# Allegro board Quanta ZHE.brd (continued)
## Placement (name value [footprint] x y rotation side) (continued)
PC221  *0.1u/16V_4  [C0402]  140.49 24.94 0 bottom
PC222  0.1u/50V_6  [C0603]  151.42 24.56 90 bottom
PC223  *0.1u/16V_4  [C0402]  140.49 23.93 0 bottom
PC224  22u/6.3V_6  [C0603]  148.75 22.5 90 bottom
PC225  0.1u/16V_4  [C0402]  141.89 20.88 270 bottom
PC226  0.033u/16V_4  [C0402]  143.92 20.88 90 bottom
PC227  10u/6.3V_6  [C0603]  146.84 20.75 90 bottom
PC228  22u/6.3V_8  [C0805]  149 19.35 270 bottom
PC229  22u/6.3V_8  [C0805]  151.04 19.35 270 bottom
PC230  22u/6.3V_6  [C0603]  164.62 17.83 180 bottom
PC231  22u/6.3V_6  [C0603]  164.62 16.31 180 bottom
PC232  10u/25V_8  [C0805]  137.7 14.91 270 bottom
PC233  2200p/50V_4  [C0402]  139.22 14.91 270 bottom
PC234  *47p/50V_4  [C0402]  100.36 15.29 90 bottom
PC235  *47p/50V_4  [C0402]  102.52 14.78 90 bottom
PC236  22u/6.3V_6  [C0603]  164.62 14.78 180 bottom
PC237  22u/25V_8  [C0805]  88.83 13.38 0 bottom
PD1  P4SMAFJ20A  [D-3_8X2_5]  29.95 100.84 270 top
PD2  PDZ5.6B  [DSM]  103.03 13.51 270 top
PD3  PDZ5.6B  [DSM]  104.98 13.51 270 top
PD4  SV1040  [D-TO277_213-6_1X4_3]  18.12 77.9 90 bottom
PJ1  *S_3720  [SHORT3720]  46.13 79.81 270 top
PJ2  *S_3720  [SHORT3720]  29.5 73.33 270 top
PJ3  *S_3720  [SHORT3720]  148.11 72.06 180 top
PJ4  *S_3720  [SHORT3720]  117.89 15.92 0 top
PJ5  CI2504P1H02-RB-NH  [50320-0040N-001-4P-L-SMT]  30.04 100.11 90 bottom
PJ6  *S_3720  [SHORT3720]  125.89 77.34 90 bottom
PJ7  *S_3720  [SHORT3720]  124.7 66.39 180 bottom
PJ8  *S_3720  [SHORT3720]  136.68 65.45 90 bottom
PJ9  *S_3720  [SHORT3720]  24.8 64.95 270 bottom
PJ10  *S_3720  [SHORT3720]  155.86 60.25 0 bottom
PJ11  *S_3720  [SHORT3720]  161.96 39.67 90 bottom
PJ12  *S_3720  [SHORT3720]  155.99 37.9 180 bottom
PJ13  *S_3720  [SHORT3720]  155.99 32.31 180 bottom
PJ14  *S_3720  [SHORT3720]  144.18 17.58 270 bottom
PJ15  *S_3720  [SHORT3720]  161.07 17.45 270 bottom
PJ16  50458-00801-V02  [50458-00801-V02-8P-L]  98.35 7.52 180 bottom
PL1  2.2uH_2.5x2.0x1.2  [L2_5X2-1_2H]  114.08 13.26 0 top
PL2  0.15uH/36A_7x7x4  [L6_6X6_6-3_8]  58.96 80.31 0 bottom
PL3  0.68uH_7x7x3  [CHOKE-PCMC063T-3R3MN-SMT]  136.56 78.92 180 bottom
PL4  0.47uH/17.5A_7X7X3  [CHOKE-PCMC063T-3R3MN-SMT]  41.94 74.98 0 bottom
PL5  1uH_7x7x3  [CHOKE-PCMC063T-3R3MN-SMT]  127.84 71.68 180 bottom
PL6  2.2uH_2.5x2.0x1.2  [L2_5X2-1_2H]  21.24 64.18 0 bottom
PL7  1uH/11A_7x7x3  [CHOKE-PCMC063T-3R3MN-SMT]  155.73 53.9 90 bottom
PL8  1uH/11A_7x7x3  [CHOKE-PCMC063T-3R3MN-SMT]  162.59 24.18 270 bottom
PL9  1uH/11A_7x7x3  [CHOKE-PCMC063T-3R3MN-SMT]  155.61 21.39 270 bottom
PL10  6.8uH_7x7x3  [CHOKE-PCMC063T-3R3MN-SMT]  128.18 15.42 180 bottom
PQ1  2N7002K  [SOT23_213-3_3-2]  109.96 84 270 top
PQ2  AO3404  [SOT23_213-3_3-2]  143.03 70.15 90 top
PQ3  VL@2N7002K  [SOT23_213-3_3-2]  169.93 65.3 270 top
PQ4  VL@DDTC144EUA-7-F  [UMT_213-3-1_3]  166.61 64.95 90 top
PQ5  VL@2N7002K  [SOT23_213-3_3-2]  158.78 62.15 270 top
PQ6  VL@AO3415  [SOT23_213-3_3-2]  162.49 62.15 270 top
PQ7  2N7002K  [SOT23_213-3_3-2]  157.13 57.96 270 top
PQ8  2N7002K  [SOT23_213-3_3-2]  158.88 53.47 180 top
PQ9  *2N7002K  [SOT23_213-3_3-2]  115.98 37.26 90 top
PQ10  *AO3404  [SOT23_213-3_3-2]  116.11 33.07 90 top
PQ11  2N7002K  [SOT23_213-3_3-2]  158.66 32.69 270 top
PQ12  DDTC144EUA-7-F  [UMT_213-3-1_3]  155.28 32.31 270 top
PQ13  AON6414AL  [POWER-5_2X5_55-1_27-5P]  127.54 15.29 180 top
PQ14  AON6414AL  [POWER-5_2X5_55-1_27-5P]  50.96 75.87 0 bottom
PQ15  AON7752  [DFN-8L-3X3-65-5P-0_9H]  35.21 74.85 180 bottom
PQ16  AON6792  [POWER-5_2X5_55-1_27-5P]  57.82 73.71 0 bottom
PQ17  AON6414AL  [POWER-5_2X5_55-1_27-5P]  19.18 71.5 0 bottom
PQ18  AON7410  [DFN-8L-3X3-65-5P-0_9H]  36.35 71.17 0 bottom
PQ19  AO3404  [SOT23_213-3_3-2]  24.42 60.88 270 bottom
PQ20  AON7752  [DFN-8L-3X3-65-5P-0_9H]  153.37 28.17 180 bottom
PQ21  AON7410  [DFN-8L-3X3-65-5P-0_9H]  157.26 27.99 270 bottom
PQ22  AON7410  [DFN-8L-3X3-65-5P-0_9H]  134.65 17.74 0 bottom
PQ23  AON7410  [DFN-8L-3X3-65-5P-0_9H]  134.65 13.93 180 bottom
PQ24  *2N7002K  [SOT23_213-3_3-2]  138.21 7.42 90 bottom
PR1  22_5%_8  [R0805]  110.73 86.92 0 top
PR2  100_1%_4  [R0402]  65.56 85.14 0 top
PR3  100_1%_4  [R0402]  65.56 84.12 180 top
PR4  10_5%_6  [R0603]  143.16 83.23 180 top
PR5  2.2_5%_6  [R0603]  143.16 81.81 180 top
PR6  *S_4  [S0402]  148.5 78.79 90 top
PR7  *S_4  [S0402]  149.51 78.79 90 top
PR8  *0_5%_4  [R0402]  148.5 77.01 90 top
PR9  100K_1%_4  [R0402]  149.51 77.01 270 top
PR10  *S_4  [S0402]  41.94 76.12 90 top
PR11  *S_4  [S0402]  42.96 76.12 270 top
PR12  *2.2_5%_6  [R0603]  56.42 73.71 180 top
PR13  2.2_5%_6  [R0603]  56.42 72.19 180 top
PR14  3.3_5%_6  [R0603]  59.21 72.19 0 top
PR15  4.02K_1%_4  [R0402]  16.67 71.42 0 top
PR16  47.5K_1%_4  [R0402]  27.72 70.41 0 top
PR17  VL@1M_5%_6  [R0603]  175.93 70.41 0 top
PR18  *160_1%_4  [R0402]  49.94 70.03 0 top
PR19  *S_6  [S0603]  39.66 69.77 270 top
PR20  VL@1M_5%_6  [R0603]  173.51 69.65 270 top
PR21  324_1%_4  [R0402]  27.72 69.39 0 top
PR22  VL@22_5%_8  [R0805]  171.74 69.26 90 top
PR23  *200_1%_4  [R0402]  48.29 68.76 90 top
PR24  6.04K_1%_4  [R0402]  27.72 68.25 0 top
PR25  *S_4  [S0402]  38.13 67.56 180 top
PR26  *240_1%_4  [R0402]  49.82 67.49 0 top
PR27  3.83K_1%_4  [R0402]  27.72 67.11 0 top
PR28  121K_1%_4  [R0402]  29.62 67.11 0 top
PR29  95.3_1%_4  [R0402]  38.13 66.34 180 top
PR30  3.9_1%_4  [R0402]  27.72 65.96 0 top
PR31  20.5K_1%_4  [R0402]  29.62 65.96 0 top
PR32  *0_5%_4  [R0402]  49.82 65.45 0 top
PR33  20_1%_4  [R0402]  38.13 65.2 180 top
PR34  VL@0_5%_4  [R0402]  159.16 65.07 0 top
PR35  *VL@100K_1%_6  [R0603]  163.74 65.07 180 top
PR36  30.1K_1%_4  [R0402]  29.62 64.82 180 top
PR37  VL@0_5%_4  [R0402]  161.32 64.82 180 top
PR38  22_5%_6  [R0603]  46.26 64.44 180 top
PR39  100_1%_4  [R0402]  43.21 64.06 270 top
PR40  100_1%_4  [R0402]  44.23 64.06 270 top
PR41  402_1%_4  [R0402]  27.72 63.68 180 top
PR42  *S_4  [S0402]  29.62 63.68 0 top
PR43  *S_4  [S0402]  39.91 63.55 90 top
PR44  *1K_1%_4  [R0402]  41.05 63.55 90 top
PR45  20K_1%_4  [R0402]  49.82 63.42 0 top
PR46  280_1%_4  [R0402]  48.04 62.91 0 top
PR47  402_1%_4  [R0402]  27.72 62.53 180 top
PR48  680_1%_4  [R0402]  49.82 62.41 0 top
PR49  *S_4  [S0402]  56.55 62.15 0 top
PR50  16.9K_1%_4  [R0402]  51.34 61.77 90 top
PR51  1K_1%_4  [R0402]  27.72 61.39 180 top
PR52  110_1%_4  [R0402]  49.82 61.39 0 top
PR53  57.6K_1%_4  [R0402]  32.67 61.26 270 top
PR54  *S_4  [S0402]  33.81 61.26 270 top
PR55  2.15K_1%_4  [R0402]  34.96 61.26 270 top
PR56  22.6K_1%_4  [R0402]  36.1 61.26 270 top
PR57  68K_1%_4  [R0402]  37.24 61.26 270 top
PR58  *S_4  [S0402]  56.55 61.01 0 top
PR59  22_5%_8  [R0805]  155.23 60.88 180 top
PR60  *S_4  [S0402]  30.64 60.5 90 top
PR61  *S_4  [S0402]  31.66 60.5 90 top
PR62  182_1%_4  [R0402]  51.59 59.87 90 top
PR63  *S_4  [S0402]  52.86 61.39 270 top
PR64  VL@100K_1%_4  [R0402]  161.58 59.74 0 top
PR65  221K_1%_4  [R0402]  37.62 59.61 0 top
PR66  215K_1%_4  [R0402]  34.96 59.23 270 top
PR67  100K_1%_4  [R0402]  36.1 59.23 270 top
PR68  VL@10K_5%_4  [R0402]  159.54 58.72 270 top
PR69  VL@0_5%_8  [R0805]  161.45 55.29 0 top
PR70  22_5%_8  [R0805]  161.8 52.58 270 top
PR71  *S_6  [S0603]  153.7 50.6 90 top
PR72  10_1%_6  [R0603]  155.23 50.6 90 top
PR73  *4.7_5%_6  [R0603]  158.91 49.07 0 top
PR74  *10K_1%_4  [R0402]  157.13 46.66 0 top
PR75  *1K_1%_4  [R0402]  155.61 46.28 90 top
PR76  1K_1%_4  [R0402]  156.37 44.5 0 top
PR77  1M_5%_6  [R0603]  158.66 35.86 90 top
PR78  1M_5%_6  [R0603]  153.7 35.61 90 top
PR79  *22_5%_8  [R0805]  113.06 34.97 270 top
PR80  *S_6  [S0603]  166.78 33.32 90 top
PR81  *4.7_5%_6  [R0603]  163.74 30.4 270 top
PR82  1M_5%_6  [R0603]  159.04 30.02 180 top
PR83  *100K_1%_6  [R0603]  155.35 29.77 180 top
PR84  10_1%_6  [R0603]  166.78 27.74 270 top
PR85  *4.7_5%_6  [R0603]  153.83 27.48 270 top
PR86  *4.7_5%_6  [R0603]  132.62 17.96 180 top
PR87  316K_1%_4  [R0402]  139.1 15.29 270 top
PR88  100K_1%_4  [R0402]  141.13 15.29 270 top
PR89  10K_5%_4  [R0402]  146.97 15.54 270 top
PR90  *0_5%_4  [R0402]  147.99 15.29 270 top
PR91  *S_4  [S0402]  149 15.29 270 top
PR92  *S_6  [S0603]  142.63 15.16 90 top
PR93  *S_6  [S0603]  144.23 15.16 90 top
PR94  10_1%_6  [R0603]  145.7 15.16 90 top
PR95  *S_6  [S0603]  110.4 14.65 90 top
PR96  *S_6  [S0603]  121.83 14.4 90 top
PR97  *10K_5%_4  [R0402]  148.11 13.89 180 top
PR98  *S_4  [S0402]  154.59 13.38 90 top
PR99  *S_4  [S0402]  155.61 13.38 270 top
PR100  *S_4  [S0402]  156.62 13.38 270 top
PR101  100K_5%_4  [R0402]  148.11 12.88 180 top
PR104  *S_6  [S0603]  139.35 11.86 180 top
PR105  *S_4  [S0402]  148.11 11.86 180 top
PR106  *S_4  [S0402]  148.11 10.84 180 top
PR107  *S_4  [S0402]  148.11 9.83 180 top
PR108  *100K_5%_4  [R0402]  150.15 9.83 0 top
PR109  *S_4  [S0402]  109 9.32 270 top
PR110  *0_5%_4  [R0402]  148.11 8.81 180 top
PR112  *S_4  [S0402]  148.11 7.8 180 top
PR113  *SP@15.4K_1%_4  [R0402]  150.15 7.8 180 top
PR114  100K_1%_4  [R0402]  109 7.54 270 top
PR115  15K_1%_4  [R0402]  110.27 7.54 90 top
PR116  47.5K_1%_4  [R0402]  111.28 7.54 270 top
PR117  *S_4  [S0402]  112.3 7.54 270 top
PR118  *S_4  [S0402]  113.32 7.54 90 top
PR119  10K_5%_4  [R0402]  114.33 7.54 90 top
PR120  *0_5%_4  [R0402]  115.35 7.54 270 top
PR121  4.02K_1%_4  [R0402]  143.67 6.91 270 top
PR122  *S_4  [S0402]  144.69 6.91 90 top
PR123  137K_1%_4  [R0402]  145.7 6.91 270 top
PR124  *S_4  [S0402]  146.72 6.91 90 top
PR125  20_5%_12  [R1206]  138.97 5.64 90 top
PR126  100K_1%_4  [R0402]  143.67 4.88 90 top
PR127  100K_1%_4  [R0402]  144.69 4.88 270 top
PR128  866K_1%_4  [R0402]  145.7 4.88 270 top
PR130  *S_4  [S0402]  110.01 86.79 0 bottom
PR131  150_1%_4  [R0402]  113.71 86.92 90 bottom
PR132  *4.7_5%_6  [R0603]  139.61 83.11 0 bottom
PR133  30.1K_1%_4  [R0402]  109.38 82.47 180 bottom
PR134  1K_NTC_4_3%  [R0402]  43.34 78.92 0 bottom
PR135  *S_4  [S0402]  64.93 78.03 180 bottom
PR136  1K_NTC_4_3%  [R0402]  66.83 78.03 0 bottom
PR137  *2.2_5%_6  [R0603]  36.1 77.52 0 bottom
PR138  *S_4  [S0402]  148.24 77.27 90 bottom
PR139  *S_4  [S0402]  150.27 77.27 90 bottom
PR140  *S_4  [S0402]  64.93 77.01 180 bottom
PR141  6.34K_1%_4  [R0402]  148.24 75.49 270 bottom
PR142  20K_1%_4  [R0402]  150.27 75.49 270 bottom
PR143  100K_1%_4  [R0402]  135.03 74.98 0 bottom
PR144  *S_4  [S0402]  137.95 74.98 180 bottom
PR145  10K_1%_4  [R0402]  139.86 74.98 180 bottom
PR146  73.2K_1%_4  [R0402]  146.34 74.34 0 bottom
PR147  *S_4  [S0402]  133.64 73.96 270 bottom
PR148  *S_4  [S0402]  136.81 73.96 0 bottom
PR149  10K_1%_4  [R0402]  139.22 72.95 180 bottom
PR150  0.01_1%_0612  [RC3216]  24.57 72.21 270 bottom
PR151  10K_1%_4  [R0402]  49.82 71.55 0 bottom
PR152  *S_6  [S0603]  52.23 71.04 90 bottom
PR154  1K_1%_4  [R0402]  61.88 70.41 180 bottom
PR155  57.6K_1%_4  [R0402]  63.91 69.01 90 bottom
PR156  *S_4  [S0402]  49.82 70.03 0 bottom
PR157  121K_1%_4  [R0402]  58.58 69.77 270 bottom
PR158  2.2_5%_6  [R0603]  30.64 69.77 180 bottom
PR159  100K_NTC_4_1%  [R0402]  39.91 69.77 270 bottom
PR160  100K_NTC_4_1%  [R0402]  57.56 69.77 270 bottom
PR161  9.53K_1%_4  [R0402]  59.6 69.77 90 bottom
PR162  0_5%_4  [R0402]  61.88 69.39 180 bottom
PR163  *S_4  [S0402]  23.88 69.34 270 bottom
PR164  *S_4  [S0402]  24.97 69.34 270 bottom
PR166  95.3_1%_4  [R0402]  49.82 69.01 0 bottom
PR167  10_5%_6  [R0603]  139.08 68.79 270 bottom
PR168  3.3_5%_6  [R0603]  30.64 68.25 180 bottom
PR169  3.9_1%_4  [R0402]  59.98 68.25 180 bottom
PR170  *2.2_5%_6  [R0603]  132.87 68.25 90 bottom
PR171  *S_4  [S0402]  49.82 67.87 0 bottom
PR172  40.2K_1%_4  [R0402]  58.45 67.87 90 bottom
PR173  110K_5%_4  [R0402]  17 67.84 180 bottom
PR174  *S_4  [S0402]  157.39 67.61 180 bottom
PR175  10K_1%_4  [R0402]  38.13 67.49 180 bottom
PR176  21.5K_1%_4  [R0402]  59.98 67.23 180 bottom
PR177  *S_4  [S0402]  61.88 67.23 180 bottom
PR178  *S_8  [S0805]  160.43 66.85 180 bottom
PR179  20_1%_4  [R0402]  49.82 66.72 0 bottom
PR180  *S_4  [S0402]  157.39 66.6 0 bottom
PR181  160_1%_4  [R0402]  40.16 66.34 0 bottom
PR182  365_1%_4  [R0402]  61.5 66.09 0 bottom
PR183  604_1%_4  [R0402]  58.33 65.71 90 bottom
PR184  *S_4  [S0402]  157.39 65.58 180 bottom
PR185  *10K_1%_4  [R0402]  49.82 65.45 180 bottom
PR186  *S_4  [S0402]  38.13 65.2 180 bottom
PR187  *200_1%_4  [R0402]  40.16 65.2 0 bottom
PR188  *S_4  [S0402]  160.81 64.82 0 bottom
PR189  *S_4  [S0402]  46.13 64.44 0 bottom
PR190  *S_4  [S0402]  48.04 64.44 0 bottom
PR191  *S_4  [S0402]  38.13 64.06 180 bottom
PR192  240_1%_4  [R0402]  40.16 64.06 0 bottom
PR194  10K_1%_4  [R0402]  58.33 63.93 90 bottom
PR195  100K_5%_4  [R0402]  160.81 63.8 0 bottom
PR196  9.09K_1%_4  [R0402]  33.81 63.68 270 bottom
PR197  3.83K_1%_4  [R0402]  34.96 63.68 270 bottom
PR198  365_1%_4  [R0402]  49.82 63.42 180 bottom
PR199  20_1%_4  [R0402]  51.59 63.04 180 bottom
PR200  681_1%_4  [R0402]  53.37 63.04 180 bottom
PR201  24.9K_1%_4  [R0402]  47.66 62.53 90 bottom
PR202  *20K_1%_4  [R0402]  46.13 62.79 180 bottom
PR204  35.7K_1%_4  [R0402]  56.8 62.53 270 bottom
PR205  *S_6  [S0603]  21.37 61.26 270 bottom
PR206  22_5%_6  [R0603]  38.77 62.03 90 bottom
PR207  2.94K_1%_4  [R0402]  51.59 62.03 180 bottom
PR208  38.3K_1%_4  [R0402]  53.37 62.03 180 bottom
PR209  *S_4  [S0402]  153.19 61.39 270 bottom
PR210  3.48K_1%_4  [R0402]  33.81 61.26 90 bottom
PR211  12.4K_1%_4  [R0402]  34.96 61.26 90 bottom
PR212  11.5K_1%_4  [R0402]  36.1 61.26 90 bottom
PR213  210_1%_4  [R0402]  37.24 61.26 90 bottom
PR214  10K_1%_4  [R0402]  55.4 60.88 0 bottom
PR215  *S_4  [S0402]  19.46 58.85 180 bottom
PR216  15K_1%_4  [R0402]  16.49 60.3 90 bottom
PR217  30K_1%_4  [R0402]  17.48 60.3 270 bottom
PR218  100K_5%_4  [R0402]  158.66 59.61 90 bottom
PR219  10K_1%_4  [R0402]  33.81 59.23 90 bottom
PR220  100K_1%_4  [R0402]  19.59 57.33 270 bottom
PR221  *S_4  [S0402]  17.48 58.55 270 bottom
PR222  *S_4  [S0402]  166.28 57.58 180 bottom
PR223  34K_1%_4  [R0402]  160.56 52.37 0 bottom
PR224  30K_1%_4  [R0402]  160.94 50.98 270 bottom
PR225  *S_8  [S0805]  163.1 50.34 180 bottom
PR226  10K_1%_4  [R0402]  153.7 48.82 180 bottom
PR227  100K_1%_4  [R0402]  151.85 44.5 180 bottom
PR228  *S_4  [S0402]  153.7 44.5 0 bottom
PR229  *S_4  [S0402]  151.85 43.36 180 bottom
PR230  *10K_1%_4  [R0402]  153.7 42.47 180 bottom
PR231  10K_1%_4  [R0402]  152.05 41.2 270 bottom
PR232  *S_4  [S0402]  153.7 41.45 0 bottom
PR233  *S_4  [S0402]  164.88 35.48 180 bottom
PR234  *10K_1%_4  [R0402]  164.88 34.47 0 bottom
PR235  *S_4  [S0402]  167.04 33.83 180 bottom
PR236  *10K_1%_4  [R0402]  167.04 32.82 0 bottom
PR237  *1K_1%_4  [R0402]  165.64 31.16 90 bottom
PR238  1K_1%_4  [R0402]  167.04 30.78 0 bottom
PR239  *0_5%_4  [R0402]  142.27 27.48 270 bottom
PR240  *S_4  [S0402]  143.29 27.48 270 bottom
PR241  *S_4  [S0402]  145.32 27.48 90 bottom
PR242  274K_1%_4  [R0402]  146.34 27.48 90 bottom
PR243  499K_1%_4  [R0402]  138.46 25.96 180 bottom
PR244  100K_1%_4  [R0402]  140.49 25.96 180 bottom
PR245  *S_4  [S0402]  142.25 25.96 0 bottom
PR246  *S_4  [S0402]  138.46 24.94 0 bottom
PR247  2.2_5%_6  [R0603]  149.37 24.65 0 bottom
PR248  *0_5%_4  [R0402]  141.89 24.43 90 bottom
PR249  *S_4  [S0402]  138.46 23.93 0 bottom
PR250  10K_1%_4  [R0402]  140.49 22.91 0 bottom
PR251  7.87K_1%_4  [R0402]  141.89 22.66 270 bottom
PR252  *S_4  [S0402]  140.49 21.89 180 bottom
PR253  100_1%_4  [R0402]  142.91 20.88 270 bottom
PR254  *S_4  [S0402]  144.94 20.88 90 bottom
PR255  *S_4  [S0402]  164.62 19.1 180 bottom
PR256  *S_4  [S0402]  121.19 17.83 270 bottom
PR257  *S_4  [S0402]  122.21 17.83 270 bottom
PR258  1M_5%_4  [R0402]  98.71 16.81 180 bottom
PR259  0.01_1%_0612  [RC3216]  121.2 15.02 90 bottom
PR260  *0_5%_4  [R0402]  95.92 15.04 0 bottom
PR261  100_5%_4  [R0402]  97.82 15.04 180 bottom
PR262  100_5%_4  [R0402]  99.35 15.29 270 bottom
PR263  100_5%_4  [R0402]  101.38 15.29 270 bottom
PR264  *220_5%_8  [R0805]  139.1 4.11 0 bottom
PU1  RT3601EAGQW  [QFN28-4X4-4-29P-RT5041A]  33.78 65.55 90 top
PU2  BQ24780SRUYR  [QFN28-4X4-4-38P]  144.18 10.84 0 top
PU3  G5719CTB1U  [SOT23-6-2_8-95-6P-G5126TB1U]  112.05 10.21 0 top
PU4  AOZ1331DI  [SON14-3X2-4-15P-SMT]  155.61 8.69 180 top
PU5  TMP708AIDBVR  [SOT23-5-2_8-95-5P-G708]  110.78 84.63 180 bottom
PU6  G5335QT2U  [QFN23-4X4-5-25P]  144.69 77.9 270 bottom
PU7  M5671RE1U  [DFN10-3X3-5-11P-G5318]  135.8 71.55 90 bottom
PU8  VL@TPS61087DRCR  [QFN10-3X3-5-16P]  169.2 68.5 180 bottom
PU9  AOZ1331DI  [SON14-3X2-4-15P-SMT]  152.69 66.6 270 bottom
PU10  RT3601EAGQW  [QFN28-4X4-4-29P-RT5041A]  54.31 66.56 90 bottom
PU11  G5719CTB1U  [SOT23-6-2_8-95-6P-G5126TB1U]  17.92 63.75 90 bottom
PU12  G9661MF11U  [SOP8-6-1_27-9P-G5795F11U]  161.83 57.33 0 bottom
PU13  RT6256BGQUF  [QFN12-3X3-45-0_6H]  157.13 46.53 0 bottom
PU14  RT6258CGQUF  [QFN12-3X3-45-0_6H]  162.85 31.16 180 bottom
PU15  RT8231BGQW  [WQFN20-3X3-4-21P]  144.81 24.18 180 bottom
Q1  *DDTC144EUA-7-F  [UMT_213-3-1_3]  24.54 97.33 270 top
Q2  2N7002KDW  [SOT363-2_1-65-6P]  95.54 84.25 180 top
Q3  *AC@AO3413  [SOT23_213-3_3-2]  20.86 78.41 270 top
Q4  PJA138K  [SOT23_213-3_3-2]  162.08 75.74 0 top
Q5  DDTC144EUA-7-F  [UMT_213-3-1_3]  158.5 75.59 180 top
Q7  PJ4N3KDW  [SC70-2_1-65-6P]  160.31 72.95 180 top
Q11  PJA138K  [SOT23_213-3_3-2]  56.8 58.22 180 top
Q12  *PJA138K  [SOT23_213-3_3-2]  47.02 36.75 180 top
Q13  *PJA138K  [SOT23_213-3_3-2]  164.88 24.31 90 top
Q14  *AC@AO3413  [SOT23_213-3_3-2]  23.4 20.88 0 top
Q15  *SSM6N43FU  [SC70-2_1-65-6P]  52.1 14.15 270 top
Q16  *SSM6N43FU  [SC70-2_1-65-6P]  56.42 14.15 270 top
Q17  *2N7002K  [SOT23_213-3_3-2]  77.12 14.15 90 top
Q18  2N7002K  [SOT23_213-3_3-2]  80.85 14.15 90 top
Q19  2N7002K  [SOT23_213-3_3-2]  84.61 14.15 90 top
Q20  SSM6N43FU  [SC70-2_1-65-6P]  78.65 10.72 0 top
Q21  *GS@2N7002K  [SOT23_213-3_3-2]  101.51 9.7 270 top
Q22  *GS@2N7002K  [SOT23_213-3_3-2]  105.32 9.7 270 top
Q23  PJ4N3KDW  [SC70-2_1-65-6P]  64.29 8.94 270 top
Q24  PJA138K  [SOT23_213-3_3-2]  61.25 8.43 270 top
Q25  KBL@PJA3413  [SOT23_213-3_3-2]  121.14 8.43 270 top
Q26  *2N7002KDW  [SOT363-2_1-65-6P]  54.9 8.3 270 top
Q27  KBL@DDTC144EUA-7-F  [UMT_213-3-1_3]  117.81 8.3 270 top
Q28  EJ@PMST3904  [UMT_213-3-1_3]  160.69 4.62 180 top
Q29  2N7002KDW  [SOT363-2_1-65-6P]  100.87 90.09 180 bottom
Q30  PJA138K  [SOT23_213-3_3-2]  116.26 86.1 0 bottom
Q31  *PJT138K  [SOT363-2_1-65-6P-PJ4N3KDW]  78.47 80.82 270 bottom
Q32  *SSM6N43FU  [SC70-2_1-65-6P]  115.35 79.3 270 bottom
Q33  2N7002K  [SOT23_213-3_3-2]  69.37 65.71 180 bottom
Q34  2N7002K  [SOT23_213-3_3-2]  24.67 35.86 180 bottom
Q35  2N7002KDW  [SOT363-2_1-65-6P]  17.05 20.47 0 bottom
Q36  *AO3413  [SOT23_213-3_3-2]  86.39 16.53 90 bottom
Q37  *PJA138K  [SOT23_213-3_3-2]  47.02 16.46 0 bottom
Q38  *PJA138K  [SOT23_213-3_3-2]  38.64 14.4 180 bottom
R1  *S_8  [S0805]  70.64 102.28 180 top
R2  1K_5%_4  [R0402]  24.16 99.62 0 top
R3  62_1%_4  [R0402]  71.41 98.22 180 top
R4  0_5%_4  [R0402]  27.59 97.46 180 top
R5  1M_5%_4  [R0402]  70.64 97.2 0 top
R6  *0_5%_4  [R0402]  27.21 96.06 90 top
R7  *0_5%_4  [R0402]  28.2 96.06 90 top
R8  *1M_5%_4  [R0402]  67.34 94.66 0 top
R9  51_1%_4  [R0402]  69.12 94.66 180 top
R10  *10K_5%_4  [R0402]  27.59 94.54 180 top
R11  75_1%_12  [R1206]  43.97 93.78 0 top
R12  1M_5%_4  [R0402]  72.3 93.78 90 top
R13  *1M_5%_4  [R0402]  67.34 93.39 0 top
R14  62_1%_4  [R0402]  69.12 93.39 180 top
R15  51_1%_4  [R0402]  77.98 93.34 180 top
R16  *150/F_4  [R0402]  117.63 92.38 0 top
R17  *150/F_4  [R0402]  119.41 92.38 0 top
R18  *150/F_4  [R0402]  121.57 92.38 0 top
R19  *150/F_4  [R0402]  123.35 92.38 0 top
R20  *S_8  [S0805]  63.91 92.25 90 top
R21  75_1%_12  [R1206]  43.97 91.24 0 top
R22  NAC@0_5%_4  [R0402]  26.32 89.84 180 top
R23  *AC@0_5%_4  [R0402]  26.32 88.82 180 top
R24  75_1%_12  [R1206]  43.97 88.7 0 top
R25  15K_5%_4  [R0402]  26.32 87.81 0 top
R26  1K_5%_4  [R0402]  26.32 86.79 180 top
R27  *10K/F_4  [R0402]  114.21 88.19 180 top
R28  *4.7K_4  [R0402]  115.98 88.19 0 top
R29  75_1%_12  [R1206]  43.97 86.16 0 top
R30  *S_4  [S0402]  100.11 86.03 270 top
R31  *S_4  [S0402]  101.12 86.03 270 top
R32  *S_4  [S0402]  102.27 86.03 270 top
R33  *S_4  [S0402]  103.28 86.03 270 top
R34  *S_4  [S0402]  104.43 86.03 270 top
R35  *S_4  [S0402]  105.44 86.03 270 top
R36  *0_5%_4  [R0402]  26.32 85.77 0 top
R37  *3.3K_5%_4  [R0402]  89.19 85.77 90 top
R38  *10K/F_4  [R0402]  114.23 86.43 180 top
R39  *4.7K_4  [R0402]  114.23 85.42 180 top
R40  2.49K_1%_4  [R0402]  33.81 84.38 0 top
R41  *S_4  [S0402]  87.54 84.5 0 top
R42  *4.7K_4  [R0402]  114.1 84.4 180 top
R43  *4.7K_4  [R0402]  125.13 83.11 0 top
R44  *0_4  [R0402]  113.87 80.01 270 top
R45  *4.7K_4  [R0402]  125 82.09 180 top
R46  4.7K_1%_4  [R0402]  90.84 82.35 90 top
R47  *0_4  [R0402]  114.89 80.01 270 top
R48  4.7K_4  [R0402]  125.38 81.08 180 top
R49  *0_5%_8  [R0805]  23.15 81.33 270 top
R50  *S_8  [S0805]  26.58 81.46 90 top
R51  *4.7K_1%_4  [R0402]  92.74 81.33 0 top
R52  330K_5%_4  [R0402]  98.46 81.2 270 top
R53  4.7K_1%_4  [R0402]  92.74 80.31 180 top
R54  *0_5%_6  [R0603]  169.96 80.06 180 top
R55  *S_4  [S0402]  150.53 79.93 270 top
R56  10K_5%_4  [R0402]  162.47 79.93 90 top
R57  *0_5%_4  [R0402]  163.48 79.93 270 top
R58  0_5%_4  [R0402]  164.5 79.93 270 top
R59  *100K_1%_4  [R0402]  158.4 79.68 270 top
R60  10K/F_4  [R0402]  113.82 77.14 180 top
R61  *S_8  [S0805]  101.89 78.92 270 top
R62  10K_5%_4  [R0402]  92.74 78.79 0 top
R63  0_5%_8  [R0805]  160.18 78.79 90 top
R64  0_5%_8  [R0805]  24.42 78.66 180 top
R65  *10K_5%_4  [R0402]  99.98 80.06 180 top
R66  4.99K/F_4  [R0402]  115.86 79.93 270 top
R67  100K_1%_4  [R0402]  163.23 78.15 180 top
R68  *S_4  [S0402]  97.7 78.03 90 top
R69  TPS@0_6  [R0603]  165.77 77.39 180 top
R70  10K_5%_4  [R0402]  95.41 76.63 270 top
R71  *S_6  [S0603]  168.69 77.65 0 top
R72  *4.7K_1%_4  [R0402]  92.87 77.39 0 top
R73  4.7K_1%_4  [R0402]  99.73 77.84 270 top
R74  100K_1%_4  [R0402]  98.71 77.84 270 top
R75  *4.7K_1%_4  [R0402]  103.54 76.76 270 top
R77  4.7K_1%_4  [R0402]  92.87 76.38 180 top
R78  *10K/F_4  [R0402]  116.75 76.12 90 top
R79  0_4  [R0402]  117.76 76.12 270 top
R80  0_5%_8  [R0805]  23.91 75.87 270 top
R81  *S_6  [S0603]  115.48 75.61 90 top
R82  *10K_5%_4  [R0402]  155.35 75.49 0 top
R84  *4.7K_1%_4  [R0402]  102.9 75.36 180 top
R85  10K_4  [R0402]  164.62 74.47 270 top
R86  *10K_5%_4  [R0402]  165.64 75.23 270 top
R87  4.7K_1%_4  [R0402]  91.09 74.73 90 top
R88  10K_5%_4  [R0402]  92.79 74.98 270 top
R89  *AC@100K_5%_4  [R0402]  21.11 74.47 0 top
R90  150_1%_4  [R0402]  96.27 74.42 0 top
R91  4.7K_1%_4  [R0402]  102.9 74.34 180 top
R92  *S_6  [S0603]  103.92 79.17 90 top
R93  *AC@10K_5%_4  [R0402]  21.11 73.46 180 top
R94  0_5%_8  [R0805]  175.93 72.82 90 top
R95  VL@0.001_1%_3720  [RC3720-SMT]  168.05 72.31 90 top
R96  10K_5%_4  [R0402]  96.04 71.55 270 top
R97  56_1%_4  [R0402]  107.09 71.55 180 top
R98  200_1%_4  [R0402]  104.6 71.46 270 top
R99  100K_1%_4  [R0402]  89.82 70.92 270 top
R100  1K_1%_4  [R0402]  85.63 70.15 180 top
R101  100K_5%_4  [R0402]  160 70.53 270 top
R102  10K_5%_4  [R0402]  94.24 69.82 270 top
R103  0_5%_4  [R0402]  161.96 68.88 270 top
R104  1K_1%_4  [R0402]  86.52 68.63 270 top
R106  10K_5%_4  [R0402]  80.68 68.38 180 top
R107  0_5%_4  [R0402]  163.01 67.79 270 top
R108  GS@10K_5%_4  [R0402]  88.04 67.74 90 top
R109  *10K_5%_4  [R0402]  73.95 67.49 180 top
R110  *10K_5%_4  [R0402]  76.11 67.23 0 top
R111  10K_5%_4  [R0402]  78.14 67.49 0 top
R112  *10K_5%_4  [R0402]  80.68 67.23 180 top
R113  113_1%_4  [R0402]  105.44 67.13 180 top
R114  100_1%_4  [R0402]  107.22 67.18 180 top
R115  *10K_5%_4  [R0402]  160.43 66.72 0 top
R117  *4.7K_1%_4  [R0402]  78.14 66.34 0 top
R118  4.7K_1%_4  [R0402]  80.68 66.09 0 top
R119  *S_6  [S0603]  113.82 65.84 270 top
R123  *S_6  [S0603]  107.09 65.58 0 top
R125  *100K_5%_4  [R0402]  157.16 65 270 top
R126  10K_5%_4  [R0402]  154.87 64.97 180 top
R127  *10K_5%_4  [R0402]  78.01 65.2 180 top
R128  *S_6  [S0603]  85.63 64.69 0 top
R129  *S_6  [S0603]  117.38 63.8 0 top
R130  *10K_5%_4  [R0402]  73.44 63.55 0 top
R131  10K_5%_4  [R0402]  75.47 63.55 180 top
R132  *20K_1%_4  [R0402]  79.79 64.57 180 top
R133  *10K_5%_4  [R0402]  66.45 63.42 0 top
R134  *S_6  [S0603]  85.5 62.53 0 top
R135  *S_4  [S0402]  166.28 62.66 180 top
R136  10K_5%_4  [R0402]  66.45 62.41 180 top
R137  *10K_5%_4  [R0402]  68.74 62.41 0 top
R138  10K_5%_4  [R0402]  70.77 62.41 0 top
R139  10K_5%_4  [R0402]  72.55 62.41 180 top
R140  *10K_5%_4  [R0402]  75.47 62.41 0 top
R141  4.7K_1%_4  [R0402]  78.52 62.41 0 top
R142  *10K_5%_4  [R0402]  80.42 62.41 0 top
R143  *S_6  [S0603]  117.38 62.28 0 top
R144  0_5%_4  [R0402]  135.03 62.28 270 top
R145  240_1%_4  [R0402]  136.18 62.28 270 top
R146  *0_5%_4  [R0402]  140.75 62.28 90 top
R147  0_5%_4  [R0402]  141.89 62.28 270 top
R148  *S_4  [S0402]  166.28 61.64 180 top
R149  *10K_5%_4  [R0402]  67.85 61.39 0 top
R150  10K_5%_4  [R0402]  70.77 61.39 180 top
R151  10K_5%_4  [R0402]  73.44 61.39 180 top
R152  *10K_5%_4  [R0402]  75.47 61.39 0 top
R153  *S_6  [S0603]  113.57 61.14 0 top
R154  *S_4  [S0402]  166.28 60.63 180 top
R155  10K_5%_4  [R0402]  68.61 60.25 180 top
R156  *10K_5%_4  [R0402]  71.53 60.25 0 top
R157  *10K_5%_4  [R0402]  73.57 60.25 0 top
R158  *S_6  [S0603]  83.47 59.87 0 top
R159  10K_5%_4  [R0402]  75.47 60.12 180 top
R160  *S_4  [S0402]  166.28 59.61 180 top
R161  *S_6  [S0603]  116.24 59.36 90 top
R162  *S_6  [S0603]  117.76 59.36 90 top
R163  *0_5%_4  [R0402]  63.03 59.26 270 top
R164  *10K_5%_4  [R0402]  73.44 59.23 0 top
R165  10K_5%_4  [R0402]  69.12 59.1 180 top
R166  *10K_5%_4  [R0402]  71.53 59.1 0 top
R167  10K_5%_4  [R0402]  75.47 59.1 180 top
R168  *S_4  [S0402]  166.28 58.6 180 top
R169  10K_5%_4  [R0402]  54.31 58.27 90 top
R170  110_1%_4  [R0402]  97.82 57.71 90 top
R171  10K_5%_4  [R0402]  68.74 57.58 90 top
R172  *S_4  [S0402]  166.28 57.58 180 top
R173  EM@0_5%_4  [R0402]  59.98 56.79 90 top
R174  *10K_5%_4  [R0402]  54.31 56.44 270 top
R175  110_1%_4  [R0402]  98.03 55.95 270 top
R176  *10K_5%_4  [R0402]  68.74 55.68 90 top
R177  0_5%_4  [R0402]  115.35 55.68 0 top
R178  *S_4  [S0402]  150.13 51.95 90 bottom
R179  *S_8  [S0805]  82.07 54.66 0 top
R180  *0_5%_4  [R0402]  49.05 54.53 0 top
R181  1K_1%_4  [R0402]  151.47 52.32 0 bottom
R182  *0_5%_4  [R0402]  115.35 54.41 0 top
R183  EM@100K_5%_4  [R0402]  65.11 54.23 0 top
R184  *TPM@0_5%_4  [R0402]  44.23 53.9 90 top
R185  10K_5%_4  [R0402]  67.09 54.15 180 top
R186  *10K_5%_4  [R0402]  68.87 53.9 0 top
R187  *0_5%_4  [R0402]  49.18 53.39 0 top
R188  EM@0_5%_4  [R0402]  65.11 53.26 180 top
R189  *1K_1%_4  [R0402]  83.85 53.14 180 top
R190  *0_5%_4  [R0402]  56.55 52.88 180 top
R191  *10K_5%_4  [R0402]  67.09 52.88 0 top
R192  10K_5%_4  [R0402]  68.87 52.88 180 top
R193  240_1%_4  [R0402]  127.92 52.5 270 top
R194  *0_5%_4  [R0402]  49.18 52.25 0 top
R195  *TPM@4.7K_5%_4  [R0402]  44.23 52.12 270 top
R196  *S_4  [S0402]  83.85 52.12 180 top
R197  EM@10K_5%_4  [R0402]  56.55 51.74 0 top
R198  EM@10K_5%_4  [R0402]  58.45 51.74 180 top
R199  10K_5%_4  [R0402]  66.45 51.23 0 top
R200  *10K_5%_4  [R0402]  68.87 51.61 0 top
R201  *0_5%_4  [R0402]  49.18 51.23 0 top
R202  EM@0_5%_4  [R0402]  61.14 51.13 180 top
R203  4.7K_5%_4  [R0402]  172.37 50.6 0 top
R204  62_1%_4  [R0402]  174.15 50.6 0 top
R205  *TPM@10K_5%_4  [R0402]  44.23 50.34 270 top
R206  RAM@36_1%_4  [R0402]  149.66 49.43 270 top
R207  0_5%_4  [R0402]  21.88 48.56 0 top
R208  RAM@36_1%_4  [R0402]  138.16 48.44 180 top
R209  RAM@36_1%_4  [R0402]  143.16 48.44 0 top
R210  RAM@36_1%_4  [R0402]  145.73 48.41 0 top
R211  RAM@36_1%_4  [R0402]  148.65 47.93 0 top
R212  *0_5%_4  [R0402]  115.7 47.9 270 top
R213  RAM@36_1%_4  [R0402]  149.99 47.55 90 top
R214  RAM@36_1%_4  [R0402]  150.98 47.55 90 top
R215  62_1%_4  [R0402]  172.37 47.55 0 top
R216  10K_5%_4  [R0402]  20.99 47.42 0 top
R217  RAM@36_1%_4  [R0402]  145.75 47.34 0 top
R218  *36_1%_4  [R0402]  137.45 46.91 180 top
R219  *36_1%_4  [R0402]  139.41 46.91 0 top
R220  RAM@36_1%_4  [R0402]  148.65 46.81 0 top
R221  200K_5%_6  [R0603]  23.78 46.79 90 top
R222  *36_1%_4  [R0402]  140.88 46.79 270 top
R223  RAM@36_1%_4  [R0402]  142.02 46.79 270 top
R224  RAM@36_1%_4  [R0402]  144.3 46.79 90 top
R225  *S_4  [S0402]  25.43 46.61 270 top
R226  4.7K_5%_4  [R0402]  172.37 46.4 0 top
R227  *S_4  [S0402]  169.2 45.9 0 top
R228  RAM@36_1%_4  [R0402]  146.89 45.87 90 top
R229  75_1%_4  [R0402]  138.41 45.85 0 top
R230  RAM@36_1%_4  [R0402]  150.65 45.77 0 top
R231  RAM@36_1%_4  [R0402]  145.32 45.52 90 top
R232  *0_5%_4  [R0402]  44.23 45.26 0 top
R233  6.2K_1%_4  [R0402]  160.56 45.26 180 top
R234  4.7K_5%_4  [R0402]  28.1 45.01 0 top
R235  RAM@36_1%_4  [R0402]  143.69 44.78 0 top
R236  *S_4  [S0402]  25.43 44.75 270 top
R237  RAM@36_1%_4  [R0402]  140.37 44.63 270 top
R238  RAM@36_1%_4  [R0402]  142.27 44.5 270 top
R239  RAM@36_1%_4  [R0402]  148.09 44.4 270 top
R240  RAM@36_1%_4  [R0402]  149.21 44.4 270 top
R241  RAM@36_1%_4  [R0402]  150.32 44.4 270 top
R242  0_5%_4  [R0402]  131.6 44.37 270 top
R243  240_1%_4  [R0402]  132.87 44.37 270 top
R244  RAM@36_1%_4  [R0402]  151.95 44.37 270 top
R245  *S_4  [S0402]  160.56 44.25 180 top
R246  RAM@36_1%_4  [R0402]  138.44 44.19 180 top
R247  0_5%_4  [R0402]  44.23 44.12 0 top
R248  *200K_5%_6  [R0603]  23.78 43.99 270 top
R249  100K_1%_4  [R0402]  29.62 43.86 180 top
R250  4.7K_5%_4  [R0402]  31.53 43.86 0 top
R251  *S_4  [S0402]  36.35 43.81 180 top
R252  RAM@36_1%_4  [R0402]  144.66 43.81 180 top
R253  RAM@36_1%_4  [R0402]  146.54 43.81 0 top
R254  *S_4  [S0402]  49.82 43.74 0 top
R255  *S_4  [S0402]  160.56 43.23 180 top
R256  2.2_5%_6  [R0603]  41.82 43.1 0 top
R257  *0_5%_4  [R0402]  44.23 43.1 0 top
R258  10K_5%_4  [R0402]  33.43 42.85 180 top
R259  10K_5%_4  [R0402]  36.35 42.8 0 top
R260  *S_4  [S0402]  38.39 42.85 0 top
R261  *S_4  [S0402]  25.18 42.98 270 top
R262  4.7K_5%_4  [R0402]  27.72 43.48 270 top
R263  *S_4  [S0402]  29.62 42.72 0 top
R264  0_5%_4  [R0402]  147.86 42.62 180 top
R265  RAM@36_1%_4  [R0402]  149.66 42.49 90 top
R266  0_5%_4  [R0402]  49.82 42.72 0 top
R267  4.7K_5%_4  [R0402]  31.27 42.21 270 top
R268  *10K_5%_4  [R0402]  44.23 42.09 180 top
R269  10K_5%_4  [R0402]  20.99 41.96 180 top
R270  *10K_5%_4  [R0402]  23.02 41.96 0 top
R271  0_5%_4  [R0402]  36.23 41.71 0 top
R272  *0_5%_4  [R0402]  147.86 41.58 0 top
R273  *0_5%_4  [R0402]  49.82 41.71 0 top
R274  *S_4  [S0402]  38.89 41.07 0 top
R275  10K_5%_4  [R0402]  44.23 41.07 180 top
R276  *0_5%_4  [R0402]  44.23 40.05 0 top
R277  *S_8  [S0805]  157.51 39.8 0 top
R278  *S_4  [S0402]  20.61 38.91 270 top
R279  *S_8  [S0805]  90.18 38.86 90 top
R280  *S_8  [S0805]  92.34 38.86 90 top
R281  *10K_5%_4  [R0402]  44.38 37.84 270 top
R282  *S_4  [S0402]  42.93 37.49 0 top
R283  *S_4  [S0402]  169.2 36.88 0 top
R284  *10K_5%_4  [R0402]  49.82 36.75 0 top
R285  *2.2_5%_6  [R0603]  18.7 36.37 0 top
R286  2.2_5%_6  [R0603]  18.7 34.92 180 top
R287  *AC@0_5%_4  [R0402]  41.05 33.96 180 top
R289  *22_5%_4  [R0402]  20.23 33.07 180 top
R290  *S_4  [S0402]  41.82 32.94 0 top
R291  100K_5%_4  [R0402]  18.19 32.05 0 top
R292  *0_5%_4  [R0402]  41.05 31.93 0 top
R293  *10K_1%_4  [R0402]  176.18 31.55 270 top
R294  *29.4K_1%_4  [R0402]  177.32 31.55 270 top
R295  100K_5%_4  [R0402]  17.81 30.66 90 top
R296  *S_4  [S0402]  20.1 31.04 180 top
R297  100K_5%_4  [R0402]  41.05 30.91 0 top
R298  0_5%_4  [R0402]  43.09 30.91 0 top
R299  3.65K_1%_4  [R0402]  141.89 30.28 90 top
R300  *S_4  [S0402]  41.82 29.89 0 top
R301  *0_5%_4  [R0402]  114.97 29.26 180 top
R302  10K_5%_4  [R0402]  18.19 29.01 0 top
R303  *240_1%_4  [R0402]  68.31 28.24 90 top
R304  *240_1%_4  [R0402]  69.32 28.24 90 top
R305  240_1%_4  [R0402]  70.39 28.24 90 top
R306  240_1%_4  [R0402]  71.41 28.24 90 top
R307  *240_1%_4  [R0402]  72.37 28.24 270 top
R308  *240_1%_4  [R0402]  73.39 28.24 270 top
R309  240_1%_4  [R0402]  82.71 28.24 270 top
R310  *Short_0402  [S0402]  114.97 28.24 180 top
R311  2.2_5%_6  [R0603]  20.23 27.74 180 top
R312  *S_4  [S0402]  41.05 26.85 0 top
R313  *S_4  [S0402]  173.26 26.85 0 top
R314  100K_5%_4  [R0402]  20.61 26.47 0 top
R315  *S_4  [S0402]  175.93 25.83 270 top
R316  *S_4  [S0402]  177.45 25.32 0 top
R317  *S_4  [S0402]  172.12 24.43 0 top
R318  10K_5%_4  [R0402]  112.43 22.91 270 top
R319  10K_5%_4  [R0402]  113.57 22.91 270 top
R320  100K_1%_4  [R0402]  181.64 22.78 0 top
R321  *100K_5%_4  [R0402]  25.79 20.88 90 top
R322  *AC@0_5%_8  [R0805]  20.5 20.62 90 top
R323  *10K_5%_4  [R0402]  113.32 20.37 270 top
R324  *10K_5%_4  [R0402]  114.33 20.37 270 top
R325  33_5%_4  [R0402]  17.3 20.12 270 top
R326  *240_1%_4  [R0402]  69.12 20.12 90 top
R327  *240_1%_4  [R0402]  70.26 20.12 90 top
R328  *240_1%_4  [R0402]  71.53 20.12 90 top
R329  *240_1%_4  [R0402]  72.68 20.12 270 top
R330  240_1%_4  [R0402]  75.09 20.12 90 top
R331  *S_4  [S0402]  186.21 20.06 180 top
R332  240_1%_4  [R0402]  80.42 19.99 90 top
R333  *10K_5%_4  [R0402]  92.74 19.99 270 top
R334  10K_5%_4  [R0402]  93.76 19.99 90 top
R335  2.2K_5%_4  [R0402]  184.56 17.45 0 top
R336  *GS@10K_5%_4  [R0402]  105.11 16.74 0 top
R337  GS@0_6  [R0603]  101 16.69 0 top
R338  2.2K_5%_4  [R0402]  184.56 16.43 0 top
R339  0_5%_8  [R0805]  47.76 16.38 180 top
R340  200K_5%_4  [R0402]  184.56 15.42 0 top
R341  100K_1%_4  [R0402]  186.34 15.42 0 top
R342  *10K_5%_4  [R0402]  53.75 15.04 90 top
R343  *10K_5%_4  [R0402]  54.77 15.04 90 top
R344  *10K_5%_4  [R0402]  73.69 14.78 270 top
R345  0_5%_4  [R0402]  74.71 14.78 270 top
R346  *10K_5%_4  [R0402]  173.77 14.4 180 top
R347  *S_4  [S0402]  183.06 14.2 0 top
R348  1K_5%_4  [R0402]  172.37 14.02 270 top
R349  *S_6  [S0603]  169.83 13.41 180 top
R350  *10K_5%_4  [R0402]  53.75 13.26 270 top
R351  *10K_5%_4  [R0402]  54.77 13.26 270 top
R352  10K_5%_4  [R0402]  79.03 12.75 0 top
R353  10K_5%_4  [R0402]  82.71 12.75 180 top
R354  *S_4  [S0402]  176.31 12.11 90 top
R355  22_5%_4  [R0402]  177.32 12.11 270 top
R356  100K_5%_4  [R0402]  65.95 11.86 90 top
R357  20K_1%_4  [R0402]  66.96 11.86 270 top
R358  20K_1%_4  [R0402]  67.98 11.86 270 top
R359  2.2K_5%_4  [R0402]  81.82 11.35 180 top
R360  *10K_5%_4  [R0402]  84.61 11.35 90 top
R361  4.7K_5%_4  [R0402]  183.42 11.35 270 top
R362  *0_5%_4  [R0402]  180.88 10.97 180 top
R363  10K_1%_4  [R0402]  184.82 10.67 180 top
R364  *S_4  [S0402]  178.34 10.34 90 top
R365  *S_4  [S0402]  179.48 10.34 90 top
R366  0_5%_4  [R0402]  180.88 9.96 180 top
R367  *0_5%_4  [R0402]  65.95 9.83 90 top
R368  *0_5%_4  [R0402]  66.96 9.83 90 top
R369  2.2K_5%_4  [R0402]  78.65 9.07 180 top
R370  *S_6  [S0603]  171.61 8.84 0 top
R371  *10K_5%_4  [R0402]  52.61 8.69 0 top
R372  KBL@10K_5%_4  [R0402]  124.11 8.56 180 top
R373  GS@0_5%_4  [R0402]  90.46 8.43 270 top
R374  GS@4.7K_5%_4  [R0402]  91.47 8.43 90 top
R375  GS@0_5%_4  [R0402]  93.5 8.43 270 top
R376  GS@4.7K_5%_4  [R0402]  94.52 8.43 90 top
R377  GS@0_5%_4  [R0402]  95.54 8.43 270 top
R378  *S_8  [S0805]  163.1 8.43 270 top
R379  *S_8  [S0805]  165.13 8.43 270 top
R380  *S_8  [S0805]  167.16 8.43 270 top
R381  *S_8  [S0805]  169.2 8.43 270 top
R382  *10K_5%_4  [R0402]  65.95 8.05 90 top
R383  *10K_5%_4  [R0402]  52.61 7.67 0 top
R384  *100K_5%_4  [R0402]  171.08 7.42 180 top
R385  EJ@150K_1%_4  [R0402]  157.39 5.13 270 top
R386  EJ@68.1K_1%_4  [R0402]  158.4 5.13 90 top
R387  1K_1%_4  [R0402]  157.39 3.61 0 top
R388  EJ@4.7K_5%_4  [R0402]  163.99 3.61 0 top
R389  EJ@4.7K_5%_4  [R0402]  163.99 4.62 180 top
R390  4.7K_1%_4  [R0402]  123.48 90.85 180 bottom
R391  33_5%_4  [R0402]  93 90.35 0 bottom
R392  2.2K_5%_4  [R0402]  98.84 90.09 270 bottom
R393  2.2K_5%_4  [R0402]  103.16 90.09 90 bottom
R394  33_5%_4  [R0402]  92.74 89.08 0 bottom
R395  4.7K_1%_4  [R0402]  123.48 89.08 180 bottom
R396  100K_1%_4  [R0402]  116.87 90.47 90 bottom
R397  *1K_1%_4  [R0402]  98.84 88.57 180 bottom
R398  *1K_1%_4  [R0402]  102.14 88.31 0 bottom
R399  *10K_5%_4  [R0402]  104.05 88.31 180 bottom
R400  3.3K_5%_4  [R0402]  91.47 87.43 90 bottom
R401  33_5%_4  [R0402]  93 87.04 90 bottom
R402  *1K_1%_4  [R0402]  98.84 87.17 180 bottom
R403  *1K_1%_4  [R0402]  102.14 87.17 0 bottom
R404  33_5%_4  [R0402]  79.03 85.52 270 bottom
R405  *1K_1%_4  [R0402]  99.22 85.27 270 bottom
R406  *S_8  [S0805]  28.99 85.14 0 bottom
R407  3.3K_5%_4  [R0402]  78.01 85.27 90 bottom
R408  *10K_5%_4  [R0402]  106.84 84.89 90 bottom
R409  10K_5%_4  [R0402]  113.82 85.14 90 bottom
R410  33_5%_4  [R0402]  80.04 84.89 270 bottom
R411  22_5%_4  [R0402]  94.52 83.87 90 bottom
R412  22_5%_4  [R0402]  95.54 83.36 90 bottom
R413  22_5%_4  [R0402]  96.81 83.74 90 bottom
R414  33_5%_4  [R0402]  102.78 82.85 270 bottom
R415  4.7K_1%_4  [R0402]  104.81 82.85 90 bottom
R416  *4.7K_1%_4  [R0402]  105.82 82.85 270 bottom
R417  *4.7K_1%_4  [R0402]  106.84 82.85 270 bottom
R418  *4.7K_1%_4  [R0402]  107.86 82.85 270 bottom
R419  *2.2K_5%_4  [R0402]  115.6 82.09 0 bottom
R420  10K_5%_4  [R0402]  88.42 81.71 180 bottom
R421  22_5%_4  [R0402]  92.23 80.82 90 bottom
R422  22_5%_4  [R0402]  93.38 80.69 90 bottom
R423  22_5%_4  [R0402]  94.39 81.2 90 bottom
R424  22_5%_4  [R0402]  96.04 81.58 90 bottom
R425  33_5%_4  [R0402]  102.78 80.69 270 bottom
R426  33_5%_4  [R0402]  103.79 80.69 270 bottom
R427  33_5%_4  [R0402]  104.81 80.69 90 bottom
R428  4.7K_1%_4  [R0402]  105.82 80.69 90 bottom
R429  4.7K_1%_4  [R0402]  106.84 80.69 90 bottom
R430  10K_5%_4  [R0402]  107.86 80.69 90 bottom
R431  10M_5%_4  [R0402]  100.49 80.31 180 bottom
R432  *10K_5%_4  [R0402]  76.36 79.81 0 bottom
R433  10K_5%_4  [R0402]  87.92 80.31 90 bottom
R434  *10K_5%_4  [R0402]  89.19 80.31 90 bottom
R435  0_5%_4  [R0402]  117 79.3 270 bottom
R436  0_5%_4  [R0402]  113.7 79.3 90 bottom
R437  *S_4  [S0402]  116.62 88.47 0 bottom
R438  10K_5%_4  [R0402]  76.36 78.79 0 bottom
R439  0_5%_4  [R0402]  78.39 78.79 180 bottom
R440  22_5%_4  [R0402]  92.23 78.79 270 bottom
R441  22_5%_4  [R0402]  93.5 78.79 90 bottom
R442  22_5%_4  [R0402]  95.41 78.79 90 bottom
R443  4.7K_1%_4  [R0402]  101.4 78.66 90 bottom
R444  *1K_1%_4  [R0402]  99.42 78.28 180 bottom
R445  20K_1%_4  [R0402]  80.3 77.9 0 bottom
R446  1K_1%_4  [R0402]  82.07 77.9 180 bottom
R447  *0_5%_4  [R0402]  78.39 77.77 0 bottom
R448  33_5%_4  [R0402]  169.07 77.65 0 bottom
R449  33_5%_4  [R0402]  164.6 77.01 270 bottom
R450  *S_4  [S0402]  165.89 77.27 90 bottom
R451  *S_4  [S0402]  166.91 77.27 90 bottom
R452  10K_5%_4  [R0402]  80.3 76.88 180 bottom
R453  100_1%_4  [R0402]  112.94 76.76 90 bottom
R454  *2.2K_5%_4  [R0402]  115.48 76.5 180 bottom
R455  *S_6  [S0603]  121.83 76.5 270 bottom
R456  *S_6  [S0603]  123.35 76.5 270 bottom
R457  *160_1%_4  [R0402]  79.41 74.22 90 bottom
R458  0_5%_4  [R0402]  80.3 75.87 0 bottom
R459  *10K_5%_4  [R0402]  82.07 75.87 180 bottom
R460  *1K_1%_4  [R0402]  62.52 64.82 180 top
R461  100K_1%_4  [R0402]  60.61 64.06 270 top
R462  *S_4  [S0402]  80.42 74.22 270 bottom
R463  *10K_5%_4  [R0402]  82.2 73.84 180 bottom
R464  *S_4  [S0402]  151.29 73.84 270 bottom
R465  *S_4  [S0402]  152.31 73.84 270 bottom
R466  *S_4  [S0402]  154.21 73.84 270 bottom
R467  *S_4  [S0402]  155.23 73.84 270 bottom
R468  68_5%_4  [R0402]  80.17 72.69 0 bottom
R469  220_5%_4  [R0402]  82.2 72.69 180 bottom
R470  240_1%_4  [R0402]  80.17 71.68 0 bottom
R471  *S_4  [S0402]  82.2 71.7 0 bottom
R472  *100K_1%_4  [R0402]  162.08 70.92 270 bottom
R473  *100K_1%_4  [R0402]  163.35 70.92 270 bottom
R474  VL@0_5%_4  [R0402]  173.39 70.66 180 bottom
R475  *1K_1%_4  [R0402]  81.19 70.53 0 bottom
R476  *4.7K_1%_4  [R0402]  80.3 69.52 0 bottom
R477  10K_5%_4  [R0402]  82.07 69.52 0 bottom
R478  VL@0_5%_4  [R0402]  173.01 69.26 270 bottom
R479  200K_1%_4  [R0402]  113.32 68.5 180 bottom
R480  10K_5%_4  [R0402]  80.68 68.38 0 bottom
R481  0_5%_4  [R0402]  113.32 67.36 0 bottom
R482  10K_5%_4  [R0402]  78.26 67.23 180 bottom
R483  2.2K_5%_4  [R0402]  80.68 67.23 180 bottom
R484  0_5%_4  [R0402]  113.32 66.34 0 bottom
R485  *10K_5%_4  [R0402]  78.14 66.09 180 bottom
R486  *S_4  [S0402]  80.68 66.09 0 bottom
R487  1K_1%_4  [R0402]  71.79 65.71 90 bottom
R488  10K_5%_4  [R0402]  72.93 65.71 270 bottom
R489  *4.7K_1%_4  [R0402]  74.07 65.71 90 bottom
R490  10K_5%_4  [R0402]  75.22 65.71 270 bottom
R491  *4.7K_1%_4  [R0402]  76.23 65.2 90 bottom
R492  *10K_5%_4  [R0402]  113.98 65.35 180 bottom
R493  VL@20K_1%_4  [R0402]  169.2 65.2 270 bottom
R494  VL@100K_1%_4  [R0402]  170.21 65.2 270 bottom
R495  10K_5%_4  [R0402]  77.25 64.69 270 bottom
R496  10K_5%_4  [R0402]  78.65 64.69 180 bottom
R497  *S_4  [S0402]  80.55 64.69 0 bottom
R498  VL@0_5%_4  [R0402]  167.8 64.69 180 bottom
R499  VL@0_5%_4  [R0402]  167.8 63.68 180 bottom
R500  VL@174K_1%_4  [R0402]  167.8 62.66 0 bottom
R501  *10K_5%_4  [R0402]  70.77 62.41 0 bottom
R502  10K_5%_4  [R0402]  72.93 62.66 180 bottom
R503  *10K_5%_4  [R0402]  75.47 62.41 0 bottom
R504  10K_5%_4  [R0402]  70.77 61.39 180 bottom
R505  10K_5%_4  [R0402]  73.44 61.39 180 bottom
R506  *10K_5%_4  [R0402]  75.47 61.39 0 bottom
R507  150_1%_4  [R0402]  114.49 60.8 180 bottom
R508  51_5%_4  [R0402]  69.5 60.25 0 bottom
R509  51_5%_4  [R0402]  71.53 60.25 0 bottom
R510  51_5%_4  [R0402]  73.57 60.25 0 bottom
R511  169_1%_4  [R0402]  75.47 60.25 180 bottom
R512  3.65K_1%_4  [R0402]  150.78 60.25 90 bottom
R513  *0_5%_4  [R0402]  44.99 59.23 90 bottom
R514  51_5%_4  [R0402]  69.5 59.1 180 bottom
R515  169_1%_4  [R0402]  71.53 59.1 0 bottom
R516  RAM@2_1%_6  [R0603]  152.18 59.1 270 bottom
R517  DB@0_5%_4  [R0402]  36.86 58.22 0 bottom
R518  24.9_1%_4  [R0402]  148.5 58.22 90 bottom
R519  *0_5%_4  [R0402]  150.78 58.22 270 bottom
R520  51_5%_4  [R0402]  69.63 57.96 0 bottom
R521  *0_5%_4  [R0402]  44.99 57.45 90 bottom
R522  *0_5%_4  [R0402]  36.86 57.07 0 bottom
R523  *10K_5%_4  [R0402]  69.63 56.95 0 bottom
R524  *TPM@0_5%_4  [R0402]  41.45 56.44 0 bottom
R525  *TPM@10K_5%_4  [R0402]  43.23 56.44 180 bottom
R526  *TPM@10K_5%_4  [R0402]  39.91 56.06 90 bottom
R527  *10K_5%_4  [R0402]  69.5 55.8 0 bottom
R528  *TPM@2.2_5%_6  [R0603]  36.74 55.68 180 bottom
R529  10K_5%_4  [R0402]  69.88 54.79 0 bottom
R530  DB@0_5%_4  [R0402]  36.74 52.63 0 bottom
R531  0_5%_4  [R0402]  127.92 52.63 270 bottom
R532  DB@0_5%_4  [R0402]  36.74 51.61 180 bottom
R533  0_5%_4  [R0402]  147.61 50.65 180 bottom
R534  *0_5%_4  [R0402]  36.74 50.47 180 bottom
R535  *0_5%_4  [R0402]  147.61 49.58 0 bottom
R536  51_1%_4  [R0402]  152.05 49.33 270 bottom
R537  DB@0_5%_4  [R0402]  36.74 49.2 180 bottom
R538  3.3K_1%_4  [R0402]  37.75 47.17 0 bottom
R539  *TPM@0_5%_4  [R0402]  43.21 46.4 0 bottom
R540  DB@0_5%_4  [R0402]  39.53 46.66 90 bottom
R541  3.3K_1%_4  [R0402]  25.43 46.53 90 bottom
R542  *S_4  [S0402]  37.75 46.02 180 bottom
R543  *10K_5%_4  [R0402]  37.75 44.75 180 bottom
R544  DB@0_5%_4  [R0402]  39.53 44.75 90 bottom
R545  *0_5%_4  [R0402]  39.53 42.85 270 bottom
R546  *10K_5%_4  [R0402]  25.18 43.36 90 bottom
R547  3.3K_1%_4  [R0402]  37.37 42.47 0 bottom
R548  *S_4  [S0402]  25.81 41.2 0 bottom
R549  33_5%_4  [R0402]  26.07 39.8 0 bottom
R550  100K_5%_4  [R0402]  26.7 38.15 0 bottom
R551  10K_5%_4  [R0402]  20.61 36.12 90 bottom
R552  *S_4  [S0402]  168.82 32.82 180 bottom
R553  *S_4  [S0402]  168.82 31.8 180 bottom
R554  *33_5%_4  [R0402]  30.64 31.67 270 bottom
R555  0_5%_4  [R0402]  133.51 30.28 90 bottom
R556  240_1%_4  [R0402]  135.92 30.28 90 bottom
R557  0_5%_4  [R0402]  140.75 30.28 90 bottom
R558  *0_5%_4  [R0402]  141.89 30.28 270 bottom
R559  33_5%_4  [R0402]  36.1 30.28 90 bottom
R560  0_5%_4  [R0402]  31.74 29.77 90 bottom
R561  0_5%_4  [R0402]  32.8 29.77 90 bottom
R562  *4.7K_5%_4  [R0402]  127.41 28.24 270 bottom
R563  *SRD@4.7K_5%_4  [R0402]  128.43 28.24 90 bottom
R564  *SRD@4.7K_5%_4  [R0402]  129.45 28.24 90 bottom
R565  *SRD@4.7K_5%_4  [R0402]  130.46 28.24 270 bottom
R566  *SRD@4.7K_5%_4  [R0402]  131.48 28.24 270 bottom
R567  *SRD@4.7K_5%_4  [R0402]  132.49 28.24 90 bottom
R568  *4.7K_5%_4  [R0402]  133.51 28.24 270 bottom
R569  *SRD@4.7K_5%_4  [R0402]  134.53 28.24 90 bottom
R570  *S_4  [S0402]  168.82 27.74 180 bottom
R571  *S_4  [S0402]  168.82 26.72 180 bottom
R572  *0_5%_4  [R0402]  18.45 23.03 270 bottom
R573  *4.7K_5%_4  [R0402]  17.05 22.45 180 bottom
R574  *2K_1%_4  [R0402]  168.82 21 0 bottom
R575  4.99K/F_4  [R0402]  125.89 20.62 90 bottom
R576  *SRD@4.7K_5%_4  [R0402]  126.91 20.62 270 bottom
R577  *SRD@4.7K_5%_4  [R0402]  127.92 20.62 90 bottom
R578  *SRD@4.7K_5%_4  [R0402]  128.94 20.62 270 bottom
R579  *SRD@4.7K_5%_4  [R0402]  129.95 20.62 90 bottom
R580  4.7K_5%_4  [R0402]  130.97 20.62 270 bottom
R581  *SRD@4.7K_5%_4  [R0402]  131.99 20.62 90 bottom
R582  *S_4  [S0402]  137.19 20.62 270 bottom
R583  10K_4  [R0402]  17.18 18.59 180 bottom
R584  *0_5%_4  [R0402]  81.06 17.83 180 bottom
R585  *4.7K_5%_4  [R0402]  45.32 18.21 180 bottom
R586  *330_5%_4  [R0402]  168.82 17.7 0 bottom
R587  2_1%_6  [R0603]  93.63 17.58 0 bottom
R588  *0_5%_4  [R0402]  90.71 17.45 90 bottom
R589  3.65K_1%_4  [R0402]  91.73 17.45 90 bottom
R590  *S_4  [S0402]  31.53 16.81 90 bottom
R591  *S_4  [S0402]  32.54 16.81 90 bottom
R592  *0_5%_4  [R0402]  44.1 16.81 90 bottom
R593  *S_4  [S0402]  168.82 16.69 0 bottom
R594  24.9_1%_4  [R0402]  95.92 16.56 180 bottom
R595  *S_4  [S0402]  21.62 15.16 90 bottom
R596  *S_4  [S0402]  22.64 15.16 90 bottom
R597  *S_4  [S0402]  29.12 15.16 90 bottom
R598  *S_4  [S0402]  30.13 15.16 90 bottom
R599  *S_4  [S0402]  33.94 13.64 90 bottom
R600  *S_4  [S0402]  34.96 13.64 90 bottom
R601  *10K_5%_4  [R0402]  36.1 16.43 270 bottom
R602  0_5%_6  [R0603]  89.06 15.92 90 bottom
R603  3.65K_1%_4  [R0402]  91.73 15.67 90 bottom
R604  *0_5%_4  [R0402]  43.07 8.81 270 bottom
R605  *0_5%_4  [R0402]  55.4 15.54 270 bottom
R606  GS@0_5%_4  [R0402]  56.42 15.54 270 bottom
R607  0_5%_8  [R0805]  18.57 15.42 180 bottom
R608  *S_4  [S0402]  168.82 15.42 180 bottom
R609  33_5%_4  [R0402]  75.09 15.29 90 bottom
R610  33_5%_4  [R0402]  78.14 15.29 90 bottom
R611  10K_5%_4  [R0402]  79.15 15.29 270 bottom
R612  10K_5%_4  [R0402]  81.19 15.29 270 bottom
R613  *0_5%_4  [R0402]  44.48 15.16 0 bottom
R614  *S_4  [S0402]  168.82 13.38 180 bottom
R615  *0_5%_8  [R0805]  18.57 13.13 0 bottom
R616  *10K_5%_4  [R0402]  40.93 12.62 270 bottom
R617  10K_5%_4  [R0402]  42.32 12.62 90 bottom
R618  *S_4  [S0402]  167.04 12.37 180 bottom
R619  0_5%_6  [R0603]  53.75 17.37 180 bottom
R620  *S_4  [S0402]  155.78 74.09 180 top
R621  *S_4  [S0402]  161.96 67.11 270 top
R622  *S_4  [S0402]  167.42 75.36 270 top
R623  10K_5%_4  [R0402]  40.29 16.05 90 bottom
R624  *0_5%_4  [R0402]  150.02 51.48 270 top
R625  1K_1%_4  [R0402]  74.5 22.45 90 top
R626  0_5%_4  [R0402]  124.75 84.5 270 top
R627  0_5%_4  [R0402]  125.76 84.5 270 top
R628  *0_5%_4  [R0402]  120.05 78.41 180 bottom
R629  *0_5%_4  [R0402]  120.05 79.42 180 bottom
R630  0_5%_4  [R0402]  113.57 82.85 270 top
R631  0_5%_4  [R0402]  114.59 82.85 270 top
R633  10_5%_4  [R0402]  99.22 76.5 0 top
R634  10_5%_4  [R0402]  81.57 63.37 0 top
R636  *0_5%_4  [R0402]  61.63 59.99 180 top
R637  *0_5%_4  [R0402]  63.79 61.77 90 top
R638  0_5%_4  [R0402]  62.52 63.8 0 top
RP1  10K_5%_10P8R  [10P8R]  39.66 20.88 0 top
SPAD1  *SPAD-RE197X197NP  [SPAD-RE197X197NP]  110.52 90.47 0 top
SPAD2  *SPAD-RE197X197NP  [SPAD-ZHP-2P-NP]  149.26 83.74 0 top
SPAD3  *SPAD-RE197X197NP  [SPAD-ZHP-2P-NP]  165.14 83.74 0 top
SPAD4  *SPAD-RE197X197NP  [SPAD-ZHP-3P-NP]  157.3 83.49 0 top
SPAD5  *SPAD-RE197X197NP  [SPAD-RE197X197NP]  149 62.92 0 top
SPAD6  *SPAD-RE315X315NP  [SPAD-RE315X315NP]  104.17 31.55 0 top
SPAD7  *SPAD-RE197X197NP  [SPAD-ZHP-1P-NP]  45.65 7.25 0 top
SPAD8  *SPAD-RE197X197NP  [SPAD-C354NP]  70.5 91 180 bottom
SPAD9  *SPAD-RE197X185NP  [SPAD-RE197X185NP]  110.32 89.81 180 bottom
SPAD10  *SPAD-RE197X197NP  [SPAD-RE197X197NP]  26.65 76.76 180 bottom
SW1  *TME-532W-Q-T/R(439)  [SW-TME-532-V-6P]  32.8 37.51 90 bottom
SW2  NDT016-G1A-KKKT  [SW-DS-A40E-4P-SMT]  121 25.75 180 bottom
SW3  TME-533B-Q-T/R  [SW-TME-533B-Q-TR-6P]  67.5 10.5 90 bottom
TP1  *TP  [TP2650]  88.81 87.3 180 top
TP2  *TP  [TP2050]  26.7 83.82 0 top
TP3  *TP  [TP2050]  28.86 84.05 0 top
TP4  *TP  [TP2050]  27.85 83.13 0 top
TP5  *TP  [TP2050]  103.05 73.48 0 top
TP6  *TP  [TP2050]  93.43 72.9 0 top
TP7  *TP  [TP2050]  88.39 72.25 0 top
TP8  *TP  [TP2050]  87.15 71.93 0 top
TP9  *TP  [TP2050]  88.73 69.59 0 top
TP10  *TP  [TP2050]  101.58 70.28 0 top
TP12  *TP  [TP2050]  84.23 69.9 0 top
TP13  *TP  [TP2050]  86.9 70.41 0 top
TP14  *TP  [TP2050]  101.33 68.93 0 top
TP15  *TP  [TP2050]  81.69 69.65 0 top
TP16  *TP  [TP2050]  97.44 58.98 0 top
TP17  *TP  [TP2050]  97.64 54.53 0 top
TP18  *TP  [TP2050]  163.48 47.42 270 top
TP19  *TP  [TP2050]  164.5 48.31 270 top
TP20  *TP  [TP2050]  167.04 48.56 270 top
TP21  *TP  [TP2050]  168.69 45.01 270 top
TP22  *TP  [TP2050]  168.69 43.74 270 top
TP23  *TP  [TP2050]  168.69 42.21 270 top
TP24  *TP  [TP2050]  28.1 41.45 0 top
TP25  *TP  [TP2050]  38.26 39.88 0 top
TP26  *TP  [TP2050]  164.88 39.95 270 top
TP27  *TP  [TP2050]  163.86 39.17 270 top
TP28  *TP  [TP2050]  167.27 39.11 270 top
TP29  *TP  [TP2050]  39.4 39.04 0 top
TP30  *TP  [TP2050]  40.8 39.04 0 top
TP31  *TP  [TP2050]  42.07 39.04 0 top
TP32  *TP  [TP2050]  20.61 37.64 0 top
TP33  *TP  [TP2050]  43.21 32.69 0 top
TP34  *TP  [TP2050]  44.38 32.18 0 top
TP35  *TP  [TP2050]  19.34 30.1 0 top
TP36  *TP  [TP2050]  20.61 30.1 0 top
TP37  *TP  [TP2050]  90.46 28.75 0 top
TP38  *TP  [TP2050]  39.68 28.12 0 top
TP39  *TP  [TP2050]  22.13 24.56 0 top
TP40  *TP  [TP2050]  30.39 21.56 0 top
TP41  *TP  [TP2050]  88.22 22.2 0 top
TP42  *TP  [TP2050]  175.55 14.4 0 top
TP43  *TP  [TP2050]  178.01 13.61 0 top
TP44  *TP  [TP2050]  148.88 6.78 0 top
TP45  *TP  [TP2650]  94.9 90.35 180 bottom
TP46  *TP  [TP2650]  91.24 89.13 180 bottom
TP47  *TP  [TP2650]  79.03 84.25 180 bottom
TP48  *TP  [TP2650]  94.14 86.28 180 bottom
TP49  *TP  [TP2650]  80.93 85.24 180 bottom
TP50  *TP  [TP2050]  96.81 78.15 180 bottom
TP51  *TP  [TP2050]  113.7 74.6 180 bottom
TP52  *TP  [TP2050]  115.09 74.6 180 bottom
TP53  *TP  [TP2050]  78.9 68.38 180 bottom
TP54  *TP  [TP2050]  74.33 66.98 180 bottom
TP55  *TP  [TP2050]  55.28 56.69 0 bottom
